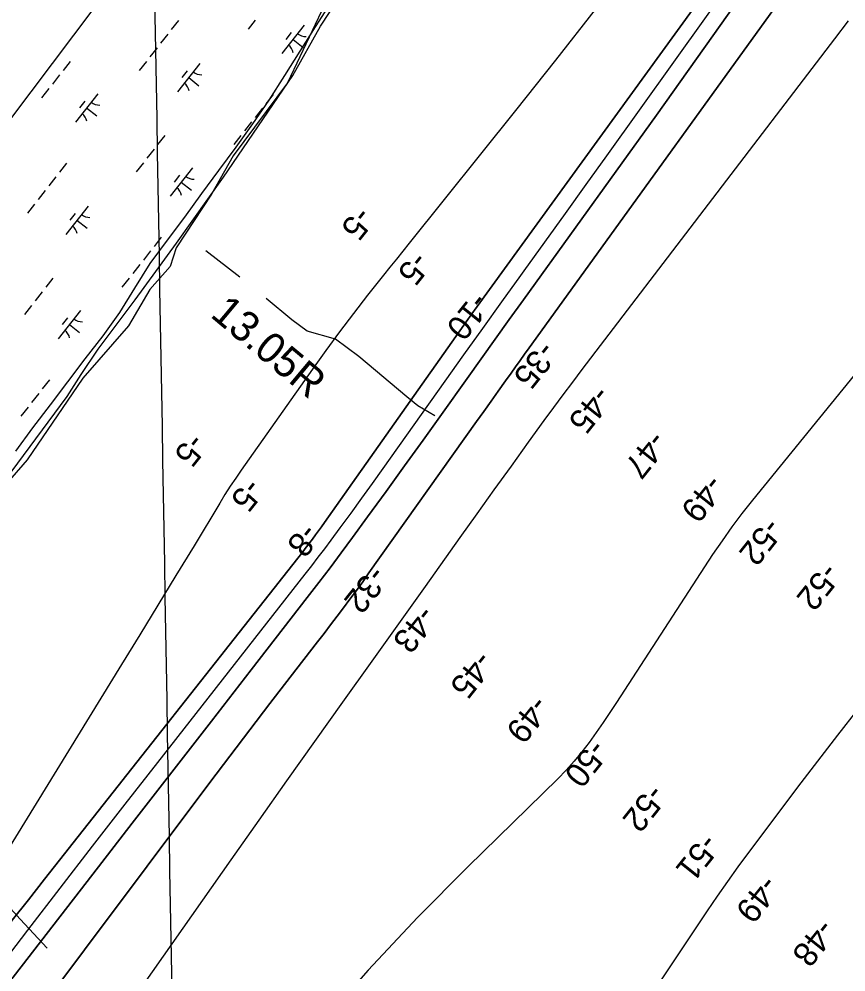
# Model space of a CAD drawing. Extents: x 3896831 to 3918110, y 171006 to 193349.
# Drawn here: x 3909409 to 3910553, y 183545 to 184864 of the extents above; entities that cross this region are included whole.
import ezdxf

# ---------------------------------------------------------------- set-up
doc = ezdxf.new("R2010")
doc.units = 0
for name, color, linetype in [('V-GRID-MAJR', 7, 'Continuous'), ('V-LEVE-TOET', 7, 'Continuous'), ('V-RIVR-EDGE', 7, 'Continuous'), ('V-RIVR-RANG', 7, 'Continuous'), ('V-RRAP-FSHR', 7, 'Continuous'), ('V-STRM-FMON', 7, 'Continuous'), ('V-TOPO-DPTH', 7, 'Continuous'), ('V-TOPO-MAJR', 7, 'Continuous'), ('V-TOPO-MINR', 7, 'Continuous'), ('V-UTIL-LINE', 7, 'Continuous'), ('V-WETL-SWMP', 7, 'Continuous')]:
    doc.layers.add(name, color=color, linetype=linetype)

msp = doc.modelspace()

# ---------------------------------------------------------------- linework, layer by layer
at = {"layer": 'V-GRID-MAJR'}
msp.add_spline([(3909752.8, 175802), (3909660.5, 181175.4), (3909556.5, 187235.6), (3909500.7, 190486.2)], degree=3, dxfattribs=at)
at = {"layer": 'V-LEVE-TOET'}
msp.add_line((3909714.1, 184506.6), (3909666.9, 184543.3), dxfattribs=at)
for points in [[(3909983.9, 184314.5), (3909960.5, 184328.6), (3909945.1, 184341), (3909878.9, 184396.8), (3909846.7, 184420.7), (3909807.4, 184432.1), (3909786.2, 184447.6), (3909750.4, 184477.2)], [(3909447.4, 183577.5), (3909410, 183617.7), (3909356.9, 183675.8), (3909308.8, 183725.9), (3909292, 183742.2), (3909255.2, 183774), (3909206.8, 183814.8), (3909184.7, 183833.9), (3909140.8, 183873)]]:
    msp.add_lwpolyline(points, dxfattribs=at)
at = {"layer": 'V-RIVR-EDGE'}
msp.add_lwpolyline([(3909831.2, 184883.7), (3909780.1, 184775.9), (3909704.9, 184674.6), (3909675.1, 184621.6), (3909625.9, 184547.3), (3909617.5, 184521.3), (3909589.6, 184489.7), (3909559.9, 184439.5), (3909496.7, 184367), (3909419.6, 184253.7), (3909355.5, 184180.3), (3909324.8, 184136.6), (3909319.2, 184117.1), (3909221.7, 183996.3), (3909135.2, 183894.1), (3909112, 183866.2), (3909075.8, 183831.8), (3909007.9, 183738), (3908938.3, 183643.2), (3908855.6, 183528)], dxfattribs=at)
at = {"layer": 'V-RRAP-FSHR'}
msp.add_lwpolyline([(3909839.9, 184887.3), (3909818.6, 184853.4), (3909797.2, 184819.6), (3909775.9, 184785.8), (3909754.5, 184752), (3909731.6, 184719.2), (3909708.8, 184686.8), (3909684.6, 184654.5), (3909661.1, 184622.8), (3909637.5, 184589.8), (3909613.4, 184557.9), (3909589.5, 184525.8), (3909568.5, 184491.7), (3909547.6, 184457.7), (3909524.5, 184425.4), (3909499.8, 184393.5), (3909475.6, 184361.7), (3909451.4, 184329.9), (3909427.3, 184298), (3909403.6, 184265.7)], dxfattribs=at)
at = {"layer": 'V-TOPO-DPTH'}
for points in [[(3909333.4, 183529.9), (3909355.2, 183558.7), (3909377.1, 183587.5), (3909399.2, 183616.2), (3909421.4, 183644.7), (3909443.7, 183673.2), (3909801.2, 184126.3), (3909803.7, 184129.5), (3909806.2, 184132.7), (3909808.6, 184136), (3909811.1, 184139.2), (3909814.7, 184144), (3909818.9, 184149.7), (3909823.1, 184155.4), (3909827.2, 184161.2), (3909831.3, 184166.9), (3910029.7, 184448), (3910030.9, 184449.6), (3910032, 184451.3), (3910034.3, 184454.5), (3910035.5, 184456.1), (3910037.8, 184459.3), (3910039, 184460.9), (3910493.3, 185088.1)], [(3910524.2, 184976), (3910114.6, 184408.7), (3910108.4, 184400), (3910102.1, 184391.3), (3910095.9, 184382.6), (3910089.6, 184373.9), (3910082, 184363.1), (3910071.9, 184349), (3910061.9, 184334.9), (3910051.9, 184320.8), (3910041.8, 184306.7), (3909892.9, 184097.1), (3909884.2, 184085), (3909875.5, 184073), (3909866.6, 184061), (3909857.7, 184049), (3909848.7, 184037.2), (3909839.7, 184025.3), (3909830.7, 184013.5), (3909821.6, 184001.7), (3909783.7, 183952.7), (3909755.7, 183916.4), (3909727.9, 183880), (3909700.2, 183843.4), (3909672.6, 183806.8), (3909412.5, 183459.3)], [(3909412.5, 183459.3), (3909672.6, 183806.8), (3909700.2, 183843.4), (3909727.9, 183880), (3909755.7, 183916.4), (3909783.7, 183952.7), (3909821.6, 184001.7), (3909830.7, 184013.5), (3909839.7, 184025.3), (3909848.7, 184037.2), (3909857.7, 184049), (3909866.6, 184061), (3909875.5, 184073), (3909884.2, 184085), (3909892.9, 184097.1), (3910041.8, 184306.7), (3910051.9, 184320.8), (3910061.9, 184334.9), (3910071.9, 184349), (3910082, 184363.1), (3910089.6, 184373.9), (3910095.9, 184382.6), (3910102.1, 184391.3), (3910108.4, 184400), (3910114.6, 184408.7), (3910524.2, 184976)], [(3910401.5, 184887.2), (3910346.2, 184809.2), (3910290.8, 184731.3), (3910235.2, 184653.6), (3910179.3, 184576), (3910106.7, 184475.2), (3910087.1, 184448.1), (3910067.6, 184420.9), (3910048.1, 184393.6), (3910028.7, 184366.3), (3909993.2, 184316.5), (3909967.8, 184280.9), (3909942.3, 184245.4), (3909916.7, 184210), (3909890.9, 184174.7), (3909869.9, 184146), (3909854.5, 184125.2), (3909839, 184104.4), (3909823.3, 184083.8), (3909807.5, 184063.3), (3909729.7, 183962.8), (3909674.9, 183892.1), (3909620.1, 183821.4), (3909565.3, 183750.7), (3909510.5, 183680), (3909365.3, 183492.7)], [(3909365.3, 183492.7), (3909510.5, 183680), (3909565.3, 183750.7), (3909620.1, 183821.4), (3909674.9, 183892.1), (3909729.7, 183962.8), (3909807.5, 184063.3), (3909823.3, 184083.8), (3909839, 184104.4), (3909854.5, 184125.2), (3909869.9, 184146), (3909890.9, 184174.7), (3909916.7, 184210), (3909942.3, 184245.4), (3909967.8, 184280.9), (3909993.2, 184316.5), (3910028.7, 184366.3), (3910048.1, 184393.6), (3910067.6, 184420.9), (3910087.1, 184448.1), (3910106.7, 184475.2), (3910179.3, 184576), (3910235.2, 184653.6), (3910290.8, 184731.3), (3910346.2, 184809.2), (3910401.5, 184887.2)], [(3910556.2, 184861.9), (3910537.2, 184836.9), (3910187.7, 184379), (3910174.5, 184361.5), (3910161.2, 184343.8), (3910148.2, 184326.1), (3910135.2, 184308.3), (3910113.4, 184278.2), (3910089.6, 184245.2), (3910065.9, 184212.2), (3910042.2, 184179.2), (3910018.6, 184146.1), (3909970.5, 184078.5), (3909952.1, 184052.6), (3909933.7, 184026.8), (3909915.2, 184000.9), (3909896.8, 183975.1), (3909856.1, 183918.1), (3909817.4, 183863.6), (3909778.8, 183809.2), (3909740.3, 183754.6), (3909701.9, 183700), (3909499.3, 183411.3)], [(3910556.2, 184861.9), (3910537.2, 184836.9), (3910187.7, 184379), (3910174.5, 184361.5), (3910161.2, 184343.8), (3910148.2, 184326.1), (3910135.2, 184308.3), (3910113.4, 184278.2), (3910089.6, 184245.2), (3910065.9, 184212.2), (3910042.2, 184179.2), (3910018.6, 184146.1), (3909970.5, 184078.5), (3909952.1, 184052.6), (3909933.7, 184026.8), (3909915.2, 184000.9), (3909896.8, 183975.1), (3909856.1, 183918.1), (3909817.4, 183863.6), (3909778.8, 183809.2), (3909740.3, 183754.6), (3909701.9, 183700), (3909499.3, 183411.3)]]:
    msp.add_lwpolyline(points, dxfattribs=at)
at = {"layer": 'V-TOPO-MAJR'}
for points in [[(3910766.5, 184619.2), (3910423.7, 184197.9), (3910409.2, 184179.5), (3910395.2, 184160.9), (3910381.8, 184141.8), (3910368.7, 184122.5), (3910235.7, 183917.7), (3910226.5, 183903.7), (3910217.1, 183889.9), (3910207.6, 183876.1), (3910197.8, 183862.5), (3910187.7, 183849.2), (3910177.1, 183836.3), (3910165.9, 183823.9), (3910154.3, 183811.9), (3910030.3, 183690.7), (3909960.2, 183619.8), (3909892, 183547.2), (3909826.4, 183472.3)], [(3910277.6, 183503), (3910361.5, 183629.2), (3910375.4, 183649.7), (3910389.5, 183670), (3910404, 183690), (3910418.6, 183709.9), (3910459.3, 183764.1), (3910486.7, 183800.4), (3910514.3, 183836.6), (3910542, 183872.7), (3910569.9, 183908.7)]]:
    msp.add_lwpolyline(points, dxfattribs=at)
at = {"layer": 'V-TOPO-MINR'}
for points in [[(3910493.3, 185088.1), (3910039, 184460.9), (3910037.8, 184459.3), (3910035.5, 184456.1), (3910034.3, 184454.5), (3910032, 184451.3), (3910030.9, 184449.6), (3910029.7, 184448), (3909831.3, 184166.9), (3909827.2, 184161.2), (3909823.1, 184155.4), (3909818.9, 184149.7), (3909814.7, 184144), (3909811.1, 184139.2), (3909808.6, 184136), (3909806.2, 184132.7), (3909803.7, 184129.5), (3909801.2, 184126.3), (3909443.7, 183673.2), (3909421.4, 183644.7), (3909399.2, 183616.2), (3909377.1, 183587.5), (3909355.2, 183558.7), (3909333.4, 183529.9)], [(3910497.9, 185061), (3910221.6, 184674.7), (3910193, 184634.9), (3910164.5, 184595), (3910135.9, 184555.2), (3910107.2, 184515.5), (3910102.6, 184509), (3910076.3, 184472.4), (3910050.1, 184435.8), (3910023.9, 184399.2), (3909997.8, 184362.5), (3909912.2, 184241.7), (3909897.5, 184221.1), (3909882.7, 184200.5), (3909867.7, 184180), (3909852.7, 184159.5), (3909840.1, 184142.5), (3909831.2, 184130.6), (3909822.3, 184118.8), (3909813.3, 184107.1), (3909804.2, 184095.4), (3909600.3, 183834.8), (3909555.1, 183776.8), (3909509.9, 183718.8), (3909465, 183660.6), (3909420.2, 183602.4), (3909361.2, 183525.4)], [(3910524.2, 184976), (3910114.6, 184408.7), (3910108.4, 184400), (3910102.1, 184391.3), (3910095.9, 184382.6), (3910089.6, 184373.9), (3910082, 184363.1), (3910071.9, 184349), (3910061.9, 184334.9), (3910051.9, 184320.8), (3910041.8, 184306.7), (3909892.9, 184097.1), (3909884.2, 184085), (3909875.5, 184073), (3909866.6, 184061), (3909857.7, 184049), (3909848.7, 184037.2), (3909839.7, 184025.3), (3909830.7, 184013.5), (3909821.6, 184001.7), (3909783.7, 183952.7), (3909755.7, 183916.4), (3909727.9, 183880), (3909700.2, 183843.4), (3909672.6, 183806.8), (3909412.5, 183459.3)], [(3910401.5, 184887.2), (3910346.2, 184809.2), (3910290.8, 184731.3), (3910235.2, 184653.6), (3910179.3, 184576), (3910106.7, 184475.2), (3910087.1, 184448.1), (3910067.6, 184420.9), (3910048.1, 184393.6), (3910028.7, 184366.3), (3909993.2, 184316.5), (3909967.8, 184280.9), (3909942.3, 184245.4), (3909916.7, 184210), (3909890.9, 184174.7), (3909869.9, 184146), (3909854.5, 184125.2), (3909839, 184104.4), (3909823.3, 184083.8), (3909807.5, 184063.3), (3909729.7, 183962.8), (3909674.9, 183892.1), (3909620.1, 183821.4), (3909565.3, 183750.7), (3909510.5, 183680), (3909365.3, 183492.7)], [(3910206, 184877.3), (3910151.2, 184807.2), (3910095.8, 184737.5), (3909948.5, 184553.9), (3909939.6, 184542.8), (3909930.8, 184531.7), (3909921.9, 184520.6), (3909913.1, 184509.5), (3909891.1, 184481.7), (3909871.5, 184456.5), (3909852.2, 184431.1), (3909833.3, 184405.3), (3909814.7, 184379.4), (3909716.2, 184239.6), (3909708.5, 184228.4), (3909700.9, 184217.1), (3909693.6, 184205.6), (3909686.5, 184194), (3909650.7, 184134.9), (3909625.7, 184093.7), (3909600.7, 184052.6), (3909575.6, 184011.5), (3909550.4, 183970.5), (3909313.7, 183585.6)], [(3910556.2, 184861.9), (3910537.2, 184836.9), (3910187.7, 184379), (3910174.5, 184361.5), (3910161.2, 184343.8), (3910148.2, 184326.1), (3910135.2, 184308.3), (3910113.4, 184278.2), (3910089.6, 184245.2), (3910065.9, 184212.2), (3910042.2, 184179.2), (3910018.6, 184146.1), (3909970.5, 184078.5), (3909952.1, 184052.6), (3909933.7, 184026.8), (3909915.2, 184000.9), (3909896.8, 183975.1), (3909856.1, 183918.1), (3909817.4, 183863.6), (3909778.8, 183809.2), (3909740.3, 183754.6), (3909701.9, 183700), (3909499.3, 183411.3)]]:
    msp.add_lwpolyline(points, dxfattribs=at)
at = {"layer": 'V-UTIL-LINE'}
msp.add_lwpolyline([(3902278.5, 176090.1), (3904647.1, 178894.7), (3905719.5, 180143.9), (3906520.8, 181098.4), (3907322.1, 182041.1), (3907534.2, 182300.3), (3908041, 182924.9), (3909514, 184881.1), (3910138.5, 185694.2), (3909821.8, 185935.5), (3909829.3, 185945.1), (3909882.7, 185907)], dxfattribs=at)
at = {"layer": 'V-WETL-SWMP'}
for p, q in [((3909825.9, 184854.1), (3909849.7, 184891.3)), ((3909629.2, 184862.1), (3909619.3, 184849.5)), ((3909735.4, 184862.7), (3909725.5, 184850.1)), ((3909803.2, 184855.7), (3909772.4, 184816.3)), ((3909614.4, 184843.2), (3909604.5, 184830.7)), ((3909785.4, 184845.5), (3909778, 184836)), ((3909787.7, 184785.9), (3909825.9, 184854.1)), ((3909787.8, 184836), (3909802, 184824.9)), ((3909599.6, 184824.4), (3909589.7, 184811.8)), ((3909479.3, 184805.6), (3909469.4, 184793)), ((3909584.8, 184805.5), (3909574.9, 184792.9)), ((3909658.9, 184802.7), (3909628, 184763.4)), ((3909641.1, 184792.5), (3909633.7, 184783.1)), ((3909464.5, 184786.7), (3909454.6, 184774.1)), ((3909643.5, 184783.1), (3909657.6, 184771.9)), ((3909691.6, 184645), (3909787.7, 184785.9)), ((3909449.7, 184767.8), (3909439.8, 184755.2)), ((3909517.5, 184760.8), (3909486.7, 184721.4)), ((3909499.7, 184750.6), (3909492.3, 184741.1)), ((3909760.1, 184759.5), (3909750.2, 184746.9)), ((3909502.1, 184741.1), (3909516.2, 184730)), ((3909745.3, 184740.6), (3909735.4, 184728)), ((3909730.5, 184721.7), (3909720.6, 184709.2)), ((3909610.2, 184703), (3909600.3, 184690.4)), ((3909715.7, 184702.9), (3909705.8, 184690.3)), ((3909595.4, 184684.1), (3909585.5, 184671.5)), ((3909474.4, 184664.6), (3909464.5, 184652)), ((3909580.6, 184665.2), (3909570.7, 184652.6)), ((3909648.4, 184658.2), (3909617.6, 184618.8)), ((3909459.6, 184645.7), (3909449.7, 184633.1)), ((3909630.6, 184648), (3909623.2, 184638.5)), ((3909626.3, 184553.8), (3909691.6, 184645)), ((3909633, 184638.5), (3909647.2, 184627.4)), ((3909444.7, 184626.8), (3909434.9, 184614.2)), ((3909429.9, 184607.9), (3909420.1, 184595.4)), ((3909504.1, 184605.2), (3909473.2, 184565.9)), ((3909486.3, 184595), (3909478.9, 184585.6)), ((3909488.7, 184585.5), (3909502.8, 184574.4)), ((3909569.4, 184475.5), (3909626.3, 184553.8)), ((3909605.3, 184562), (3909595.4, 184549.4)), ((3909590.5, 184543.1), (3909580.6, 184530.5)), ((3909575.7, 184524.2), (3909565.8, 184511.6)), ((3909455.4, 184505.5), (3909445.5, 184492.9)), ((3909560.9, 184505.3), (3909551, 184492.7)), ((3909440.6, 184486.6), (3909430.7, 184474)), ((3909518.1, 184407.2), (3909569.4, 184475.5)), ((3909425.8, 184467.7), (3909415.9, 184455.1)), ((3909493.6, 184460.7), (3909462.8, 184421.3)), ((3909475.8, 184450.5), (3909468.4, 184441)), ((3909478.2, 184441), (3909492.4, 184429.9)), ((3909494.6, 184371.8), (3909518.1, 184407.2)), ((3909475, 184341.4), (3909494.6, 184371.8)), ((3909450.5, 184364.5), (3909440.6, 184351.9)), ((3909397.8, 184236.6), (3909475, 184341.4)), ((3909435.7, 184345.6), (3909425.8, 184333)), ((3909420.9, 184326.7), (3909411, 184314.1))]:
    msp.add_line(p, q, dxfattribs=at)
for centre, start, end in [((3909805, 184857.6), 231.1403, 272.6839), ((3909770.9, 184814.1), 11.1403, 52.6839), ((3909660.7, 184804.6), 231.1403, 272.6839), ((3909626.6, 184761.2), 11.1403, 52.6839), ((3909519.3, 184762.7), 231.1403, 272.6839), ((3909485.2, 184719.2), 11.1403, 52.6839), ((3909650.2, 184660.1), 231.1403, 272.6839), ((3909616.1, 184616.6), 11.1403, 52.6839), ((3909505.9, 184607.1), 231.1403, 272.6839), ((3909471.8, 184563.6), 11.1403, 52.6839), ((3909495.4, 184462.6), 231.1403, 272.6839), ((3909461.3, 184419.1), 11.1403, 52.6839)]:
    msp.add_arc(centre, 17.6, start, end, dxfattribs=at)

# ---------------------------------------------------------------- texts
at = {"layer": 'V-RIVR-RANG'}
for s, rotation, p in [('-5', 231.3983, (3909877.4, 184606.6)), ('-5', 231.3983, (3909955.7, 184544.4)), ('-10', 231.3983, (3910038.6, 184487.9)), ('-35', 231.5421, (3910131.3, 184420.5)), ('-45', 231.5421, (3910207.5, 184358.6)), ('-47', 231.5421, (3910284.3, 184296.2)), ('-5', 231.3083, (3909646.5, 184293)), ('-5', 231.3083, (3909724.7, 184230.7)), ('-49', 231.5421, (3910363.2, 184235.6)), ('-8', 231.3083, (3909802.6, 184168)), ('-52', 231.5421, (3910443.7, 184175.8)), ('-52', 231.5421, (3910523.3, 184113.5)), ('-32', 231.4478, (3909897, 184109.5)), ('-43', 231.4478, (3909964.6, 184054.5)), ('-45', 231.4478, (3910043.7, 183991.6)), ('-49', 231.4478, (3910121.3, 183929.7)), ('-50', 231.4478, (3910201.8, 183868.6)), ('-52', 231.4478, (3910282.5, 183806.7)), ('-51', 231.4478, (3910356.2, 183738.4)), ('-49', 231.4478, (3910439.1, 183680.9)), ('-48', 231.4478, (3910517.3, 183620.2))]:
    msp.add_text(s, height=33.5, rotation=rotation, dxfattribs=at).set_placement(p)
at = {"layer": 'V-STRM-FMON'}
msp.add_text('13.05R', height=42, rotation=320.0839, dxfattribs=at).set_placement((3909671.8, 184452.9))

doc.saveas('drawing.dxf')
